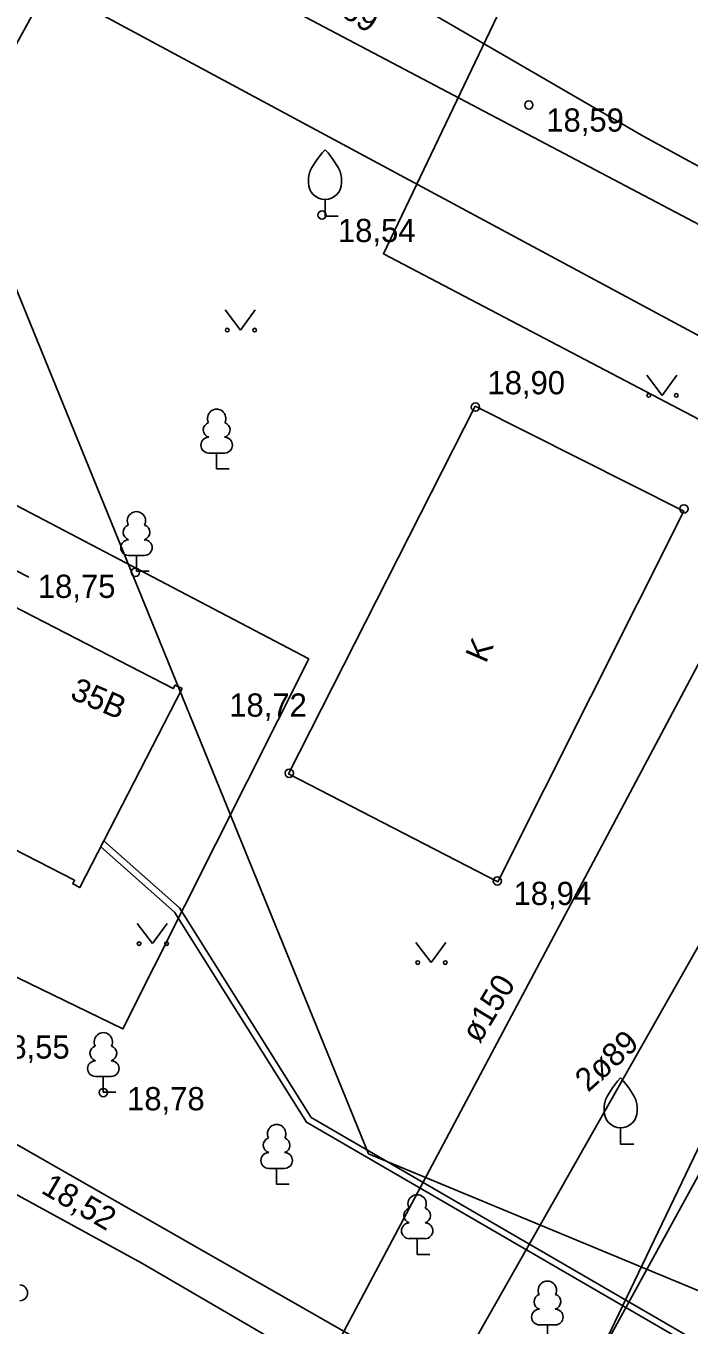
# Model space of a CAD drawing. Extents: x 713497 to 713863, y 6590062 to 6590327.
# Drawn here: x 713764.91 to 713784.91, y 6590085.09 to 6590124.29 of the extents above; entities that cross this region are included whole.
import ezdxf

# ---------------------------------------------------------------- set-up
doc = ezdxf.new("R2010")
doc.units = 0
for name, color, linetype in [('HALJASTUS', 7, 'Continuous'), ('HOONE', 7, 'Continuous'), ('HOONEDET', 7, 'Continuous'), ('KORGUS', 7, 'Continuous'), ('KPKAABEL', 7, 'Continuous'), ('MPKAABEL', 7, 'Continuous'), ('PUU', 7, 'Continuous'), ('SITRASS', 7, 'Continuous'), ('TEE', 7, 'Continuous'), ('TORU NR', 7, 'Continuous'), ('TTRASS', 7, 'Continuous'), ('Слой 1', 7, 'Continuous')]:
    doc.layers.add(name, color=color, linetype=linetype)

msp = doc.modelspace()

# ---------------------------------------------------------------- linework, layer by layer
at = {"layer": 'HALJASTUS'}
for p, q in [((713770.917, 6590115.727), (713771.38, 6590115.12)), ((713771.38, 6590115.12), (713771.826, 6590115.727)), ((713783.637, 6590113.757), (713784.1, 6590113.15)), ((713784.1, 6590113.15), (713784.546, 6590113.757)), ((713768.257, 6590097.227), (713768.72, 6590096.62)), ((713768.72, 6590096.62), (713769.166, 6590097.227)), ((713776.667, 6590096.657), (713777.13, 6590096.05)), ((713777.13, 6590096.05), (713777.576, 6590096.657))]:
    msp.add_line(p, q, dxfattribs=at)
for centre in [(713770.979, 6590115.12), (713771.808, 6590115.12), (713783.699, 6590113.15), (713784.528, 6590113.15), (713768.319, 6590096.62), (713769.148, 6590096.62), (713776.729, 6590096.05), (713777.558, 6590096.05)]:
    msp.add_circle(centre, 0.055, dxfattribs=at)
at = {"layer": 'HOONE'}
for points in [[(713789.29, 6590112.76), (713764.71, 6590125.97), (713755.23, 6590131.21)], [(713789.29, 6590112.76), (713771.86, 6590079.97)], [(713778.46, 6590112.83), (713784.76, 6590109.66), (713779.14, 6590098.48), (713772.83, 6590101.74), (713778.46, 6590112.83)]]:
    msp.add_lwpolyline(points, dxfattribs=at)
msp.add_lwpolyline([(713758.633, 6590102.366), (713761.724, 6590108.372), (713761.937, 6590108.263), (713761.882, 6590108.156), (713769.351, 6590104.312), (713769.406, 6590104.419), (713769.619, 6590104.309), (713766.533, 6590098.313), (713766.32, 6590098.423), (713766.375, 6590098.53), (713758.901, 6590102.363), (713758.846, 6590102.256)], close=True, dxfattribs=at)
at = {"layer": 'HOONEDET'}
msp.add_lwpolyline([(713761.09, 6590100.048), (713757.432, 6590101.918), (713761.332, 6590109.545), (713764.99, 6590107.675)], dxfattribs=at)
at = {"layer": 'KORGUS'}
for centre in [(713780.08, 6590121.91), (713773.84, 6590118.59), (713778.47, 6590112.8), (713784.76, 6590109.73), (713768.21, 6590107.82), (713772.85, 6590101.76), (713779.13, 6590098.51), (713767.24, 6590092.13)]:
    msp.add_circle(centre, 0.125, dxfattribs=at)
at = {"layer": 'KPKAABEL'}
msp.add_lwpolyline([(713773.44, 6590139.89), (713762.88, 6590120.59), (713775.24, 6590090.28), (713794.548, 6590082.284), (713800.542, 6590079.311), (713832.311, 6590062.302)], dxfattribs=at)
at = {"layer": 'MPKAABEL'}
for points in [[(713781.077, 6590168.981), (713778.842, 6590164.352), (713775.042, 6590156.623), (713771.019, 6590147.665), (713770.454, 6590144.893), (713769.354, 6590143.636), (713766.17, 6590138.15), (713788.39, 6590122.43), (713799.07, 6590115.1), (713794.37, 6590106.34), (713776.17, 6590073.19)], [(713767.165, 6590099.54), (713769.384, 6590097.568), (713773.372, 6590091.235), (713786.121, 6590083.841), (713799.27, 6590076.55), (713805.146, 6590074.259), (713816.203, 6590068.988), (713829.569, 6590062.302)], [(713767.259, 6590099.724), (713769.538, 6590097.698), (713773.514, 6590091.383), (713786.219, 6590084.015), (713799.356, 6590076.732), (713805.226, 6590074.443), (713816.291, 6590069.168), (713830.016, 6590062.302)]]:
    msp.add_lwpolyline(points, dxfattribs=at)
at = {"layer": 'PUU'}
for p, q in [((713773.93, 6590118.56), (713773.93, 6590119.06)), ((713774.33, 6590118.56), (713773.93, 6590118.56)), ((713770.9, 6590111.415), (713770.42, 6590111.415)), ((713770.66, 6590110.94), (713770.66, 6590111.415)), ((713771.04, 6590110.94), (713770.66, 6590110.94)), ((713768.48, 6590108.325), (713768, 6590108.325)), ((713768.24, 6590107.85), (713768.24, 6590108.325)), ((713768.62, 6590107.85), (713768.24, 6590107.85)), ((713767.48, 6590092.615), (713767, 6590092.615)), ((713767.24, 6590092.14), (713767.24, 6590092.615)), ((713767.62, 6590092.14), (713767.24, 6590092.14)), ((713782.85, 6590090.57), (713782.85, 6590091.07)), ((713783.25, 6590090.57), (713782.85, 6590090.57)), ((713772.71, 6590089.845), (713772.23, 6590089.845)), ((713772.47, 6590089.37), (713772.47, 6590089.845)), ((713772.85, 6590089.37), (713772.47, 6590089.37)), ((713776.95, 6590087.725), (713776.47, 6590087.725)), ((713776.71, 6590087.25), (713776.71, 6590087.725)), ((713777.09, 6590087.25), (713776.71, 6590087.25)), ((713780.88, 6590085.125), (713780.4, 6590085.125)), ((713780.64, 6590084.65), (713780.64, 6590085.125))]:
    msp.add_line(p, q, dxfattribs=at)
for points in [[(713773.43, 6590119.56), (713773.43, 6590119.71), (713773.44, 6590119.775), (713773.475, 6590119.905), (713773.535, 6590120.025), (713773.68, 6590120.26), (713773.84, 6590120.465), (713773.93, 6590120.56)], [(713774.43, 6590119.56), (713774.43, 6590119.71), (713774.42, 6590119.775), (713774.385, 6590119.905), (713774.325, 6590120.025), (713774.18, 6590120.26), (713774.02, 6590120.465), (713773.93, 6590120.56)], [(713782.35, 6590091.57), (713782.35, 6590091.72), (713782.36, 6590091.785), (713782.395, 6590091.915), (713782.455, 6590092.035), (713782.6, 6590092.27), (713782.76, 6590092.475), (713782.85, 6590092.57)], [(713783.35, 6590091.57), (713783.35, 6590091.72), (713783.34, 6590091.785), (713783.305, 6590091.915), (713783.245, 6590092.035), (713783.1, 6590092.27), (713782.94, 6590092.475), (713782.85, 6590092.57)]]:
    msp.add_lwpolyline(points, dxfattribs=at)
for centre, radius, start, end in [((713773.93, 6590119.56), 0.5, 180, 0), ((713770.66, 6590112.46), 0.277, 332.5799, 207.4201), ((713770.49, 6590112.113), 0.233, 109.0217, 253.1415), ((713770.83, 6590112.113), 0.233, 286.8508, 70.9859), ((713770.423, 6590111.652), 0.238, 90.0016, 269.3953), ((713770.897, 6590111.652), 0.238, 270.6047, 89.9984), ((713768.24, 6590109.37), 0.277, 332.5799, 207.4201), ((713768.07, 6590109.023), 0.233, 109.0217, 253.1415), ((713768.41, 6590109.023), 0.233, 286.8508, 70.9859), ((713768.003, 6590108.562), 0.238, 90.0016, 269.3953), ((713768.477, 6590108.562), 0.238, 270.6047, 89.9984), ((713767.24, 6590093.66), 0.277, 332.5799, 207.4201), ((713767.07, 6590093.313), 0.233, 109.0217, 253.1415), ((713767.41, 6590093.313), 0.233, 286.8508, 70.9859), ((713767.003, 6590092.852), 0.238, 90.0016, 269.3953), ((713767.477, 6590092.852), 0.238, 270.6047, 89.9984), ((713782.85, 6590091.57), 0.5, 180, 0), ((713772.47, 6590090.89), 0.277, 332.5799, 207.4201), ((713772.3, 6590090.543), 0.233, 109.0217, 253.1415), ((713772.64, 6590090.543), 0.233, 286.8508, 70.9859), ((713772.233, 6590090.082), 0.238, 90.0016, 269.3953), ((713772.707, 6590090.082), 0.238, 270.6047, 89.9984), ((713776.71, 6590088.77), 0.277, 332.5799, 207.4201), ((713776.54, 6590088.423), 0.233, 109.0217, 253.1415), ((713776.88, 6590088.423), 0.233, 286.8508, 70.9859), ((713776.473, 6590087.962), 0.238, 90.0016, 269.3953), ((713776.947, 6590087.962), 0.238, 270.6047, 89.9984), ((713780.64, 6590086.17), 0.277, 332.5799, 207.4201), ((713764.717, 6590086.092), 0.238, 270.6047, 89.9984), ((713780.47, 6590085.823), 0.233, 109.0217, 253.1415), ((713780.81, 6590085.823), 0.233, 286.8508, 70.9859), ((713780.403, 6590085.362), 0.238, 90.0016, 269.3953), ((713780.877, 6590085.362), 0.238, 270.6047, 89.9984)]:
    msp.add_arc(centre, radius, start, end, dxfattribs=at)
at = {"layer": 'SITRASS'}
for points in [[(713789.24, 6590117.86), (713783.55, 6590120.96), (713761.9, 6590133.51)], [(713789.24, 6590117.86), (713796.44, 6590113.87), (713777.82, 6590075.09), (713780.8, 6590073.4), (713780.86, 6590073.4), (713783.727, 6590071.899), (713786.611, 6590070.388), (713789.07, 6590069.1), (713785.468, 6590062.302)]]:
    msp.add_lwpolyline(points, dxfattribs=at)
at = {"layer": 'TEE'}
for points in [[(713710.467, 6590174.389), (713711.174, 6590166.795), (713710.458, 6590154.269), (713712.543, 6590141.98), (713716.21, 6590117.41), (713716.46, 6590117.25), (713750.16, 6590098.82), (713790.169, 6590075.991)], [(713725.436, 6590062.302), (713725.02, 6590064.58), (713723.58, 6590070.84), (713719.73, 6590093.93), (713718.29, 6590103.6), (713716.48, 6590115.46), (713731.16, 6590107.7), (713732.95, 6590106.76), (713749.2, 6590097.48), (713768.4, 6590086.99), (713789.423, 6590074.743), (713795.471, 6590071.359), (713795.686, 6590069.951), (713791.53, 6590062.302)]]:
    msp.add_lwpolyline(points, dxfattribs=at)
at = {"layer": 'TTRASS'}
for points in [[(713793.78, 6590113.79), (713759.97, 6590131.6)], [(713770.92, 6590070.88), (713771.86, 6590073.05), (713794.26, 6590112.52)]]:
    msp.add_lwpolyline(points, dxfattribs=at)
at = {"layer": 'Слой 1'}
for points in [[(713824.52, 6590122.4), (713811.57, 6590098.6), (713775.69, 6590117.42), (713779.01, 6590124.36), (713787.58, 6590142.43)], [(713773.44, 6590105.21), (713767.83, 6590094.05), (713754.42, 6590100.55), (713760.93, 6590111.76)]]:
    msp.add_lwpolyline(points, close=True, dxfattribs=at)

# ---------------------------------------------------------------- texts
at = {"layer": 'HOONE'}
for s, rotation, p in [('K', 66.5618, (713778.785, 6590105.048)), ('35B', 336.7943, (713766.203, 6590104.022))]:
    msp.add_text(s, height=0.7, rotation=rotation, dxfattribs=at).set_placement(p)
at = {"layer": 'KORGUS'}
for s, p in [('18,59', (713780.606, 6590121.105)), ('18,54', (713774.318, 6590117.775)), ('18,90', (713778.831, 6590113.185)), ('18,75', (713765.263, 6590107.045)), ('18,72', (713771.038, 6590103.465)), ('18,94', (713779.618, 6590097.785)), ('18,55', (713763.883, 6590093.155)), ('18,78', (713767.956, 6590091.595))]:
    msp.add_text(s, height=0.7, dxfattribs=at).set_placement(p)
msp.add_text('18,52', height=0.7, rotation=329.8372, dxfattribs=at).set_placement((713765.33, 6590089.122))
at = {"layer": 'TORU NR'}
for s, rotation, p in [('2ø89', 326.5409, (713773.463, 6590125.227)), ('ø150', 58.7707, (713778.592, 6590093.584)), ('2ø89', 42.1356, (713781.867, 6590092.119))]:
    msp.add_text(s, height=0.7, rotation=rotation, dxfattribs=at).set_placement(p)

doc.saveas('drawing.dxf')
